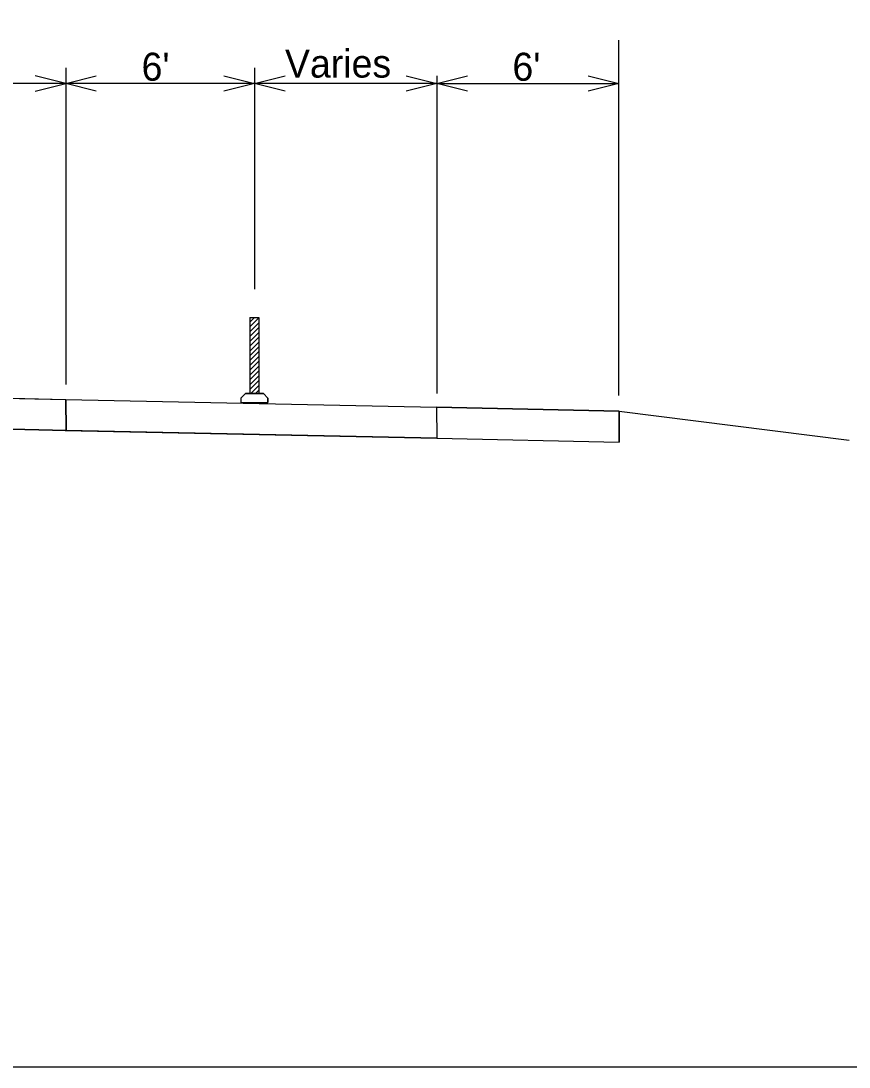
# Model space of a CAD drawing. Extents: x 10133 to 81668, y 4856 to 11018.
# Drawn here: x 11874 to 12318, y 7924 to 8484 of the extents above; entities that cross this region are included whole.
import ezdxf

# ---------------------------------------------------------------- set-up
doc = ezdxf.new("R2010")
doc.units = 0
for name, color, linetype in [('dsnStdBorder', 7, 'Continuous'), ('dsnXsPCCPavementBottom', 7, 'Continuous'), ('dsnXsShldrEarthFill', 7, 'Continuous'), ('dsnXsShldrGranular', 7, 'Continuous'), ('dsnXsShldrGranularBottom', 7, 'Continuous'), ('dsnXsShldrSpecialBackBottom', 7, 'Continuous'), ('SheetBorder', 7, 'Continuous')]:
    doc.layers.add(name, color=color, linetype=linetype)

msp = doc.modelspace()

# ---------------------------------------------------------------- linework, layer by layer
at = {"layer": 'dsnStdBorder'}
for p, q in [((11997.04, 8325.06), (12001.86, 8325.06)), ((11997.04, 8325.06), (11997.04, 8284.41)), ((11997.04, 8322.64), (11999.46, 8325.06)), ((11997.04, 8320.07), (12001.86, 8324.89)), ((12001.86, 8325.06), (12001.86, 8284.41)), ((11997.04, 8317.49), (12001.86, 8322.31)), ((11997.04, 8314.91), (12001.86, 8319.73)), ((11997.04, 8312.34), (12001.86, 8317.16)), ((11997.04, 8309.76), (12001.86, 8314.58)), ((11997.04, 8307.18), (12001.86, 8312)), ((11997.04, 8304.6), (12001.86, 8309.42)), ((11997.04, 8302.03), (12001.86, 8306.85)), ((11997.04, 8299.45), (12001.86, 8304.27)), ((11997.04, 8296.87), (12001.86, 8301.69)), ((11997.04, 8294.29), (12001.86, 8299.11)), ((11997.04, 8291.72), (12001.86, 8296.54)), ((11997.04, 8289.14), (12001.86, 8293.96)), ((11997.04, 8286.56), (12001.86, 8291.38)), ((11997.46, 8284.41), (12001.86, 8288.8)), ((12000.04, 8284.41), (12001.86, 8286.23)), ((11994.63, 8284.41), (11992.22, 8282.02)), ((11994.63, 8284.41), (11992.22, 8282.02)), ((11992.22, 8282.02), (11992.22, 8279.63)), ((11992.22, 8282.02), (11992.22, 8279.63)), ((11992.22, 8279.63), (12006.68, 8279.63)), ((11992.22, 8279.63), (12006.68, 8279.63)), ((11997.04, 8284.41), (11994.63, 8284.41)), ((11994.63, 8284.41), (12004.27, 8284.41)), ((12001.86, 8284.41), (11997.04, 8284.41)), ((12004.27, 8284.41), (12001.86, 8284.41)), ((12006.68, 8282.02), (12004.27, 8284.41)), ((12004.27, 8284.41), (12006.68, 8282.02)), ((12006.68, 8279.63), (12006.68, 8282.02)), ((12006.68, 8282.02), (12006.68, 8279.63))]:
    msp.add_line(p, q, dxfattribs=at)
at = {"layer": 'dsnXsPCCPavementBottom'}
for p, q in [((12194.51, 8283.3), (12194.51, 8473.54)), ((11898.43, 8458.67), (11898.43, 8289.29)), ((11999.45, 8458.67), (11999.45, 8340.21)), ((12097.11, 8454.43), (12097.11, 8284.38)), ((11898.43, 8450.33), (11699.76, 8450.33)), ((12097.11, 8450.33), (11898.43, 8450.33)), ((11999.45, 8450.35), (11898.71, 8450.35)), ((12097.11, 8450.33), (12194.51, 8450.33))]:
    msp.add_line(p, q, dxfattribs=at)
for points in [[(11882.04, 8446.24), (11898.43, 8450.33), (11882.04, 8454.43)], [(11914.82, 8446.24), (11898.43, 8450.33), (11914.82, 8454.43)], [(11983.06, 8454.45), (11999.45, 8450.35), (11983.06, 8446.25)], [(12015.84, 8446.25), (11999.45, 8450.35), (12015.84, 8454.45)], [(12080.72, 8454.43), (12097.11, 8450.33), (12080.72, 8446.24)], [(12113.5, 8446.24), (12097.11, 8450.33), (12113.5, 8454.43)], [(12178.12, 8454.43), (12194.51, 8450.33), (12178.12, 8446.24)]]:
    msp.add_lwpolyline(points, dxfattribs=at)
at = {"layer": 'dsnXsShldrGranular'}
msp.add_line((11898.67, 8264.73), (11699.65, 8268.96), dxfattribs=at)
msp.add_lwpolyline([(11700, 8285.51), (11898.43, 8281.3), (11898.67, 8264.73)], dxfattribs=at)
for points in [[(11898.43, 8281.3), (12096.87, 8277.08), (12097.11, 8260.51), (11898.67, 8264.73)], [(12194.62, 8275), (12096.87, 8277.08), (12097.11, 8260.51), (12194.62, 8258.4)]]:
    msp.add_lwpolyline(points, close=True, dxfattribs=at)
at = {"layer": 'dsnXsShldrGranularBottom'}
for p, q in [((11700, 8285.51), (11898.43, 8281.3)), ((11898.43, 8281.3), (11898.67, 8264.73)), ((11898.43, 8281.3), (12096.87, 8277.08)), ((12096.87, 8277.08), (12097.11, 8260.51)), ((12096.87, 8277.08), (12097.11, 8260.51)), ((12096.87, 8277.08), (12097.11, 8260.51)), ((12194.62, 8275), (12317.73, 8259.53)), ((11699.65, 8268.96), (11898.67, 8264.73)), ((11898.08, 8264.74), (12097.11, 8260.51))]:
    msp.add_line(p, q, dxfattribs=at)
at = {"layer": 'dsnXsShldrSpecialBackBottom'}
for p, q in [((12096.87, 8277.08), (12194.62, 8275)), ((12194.62, 8275), (12194.62, 8258.4)), ((12097.11, 8260.51), (12194.62, 8258.4))]:
    msp.add_line(p, q, dxfattribs=at)
at = {"layer": 'SheetBorder'}
msp.add_lwpolyline([(10132.52, 9944.02), (13267.53, 9944.02), (13267.53, 7924.02), (10132.52, 7924.02)], close=True, dxfattribs=at)

# ---------------------------------------------------------------- texts
at = {"layer": 'dsnXsShldrEarthFill'}
for s, p in [("6'", (11939.04, 8451.82)), ('Varies', (12015.79, 8453.49))]:
    msp.add_text(s, height=15, dxfattribs=at).set_placement(p)
msp.add_text("6'", height=15, rotation=0, dxfattribs=at).set_placement((12137.54, 8451.8))

doc.saveas('drawing.dxf')
